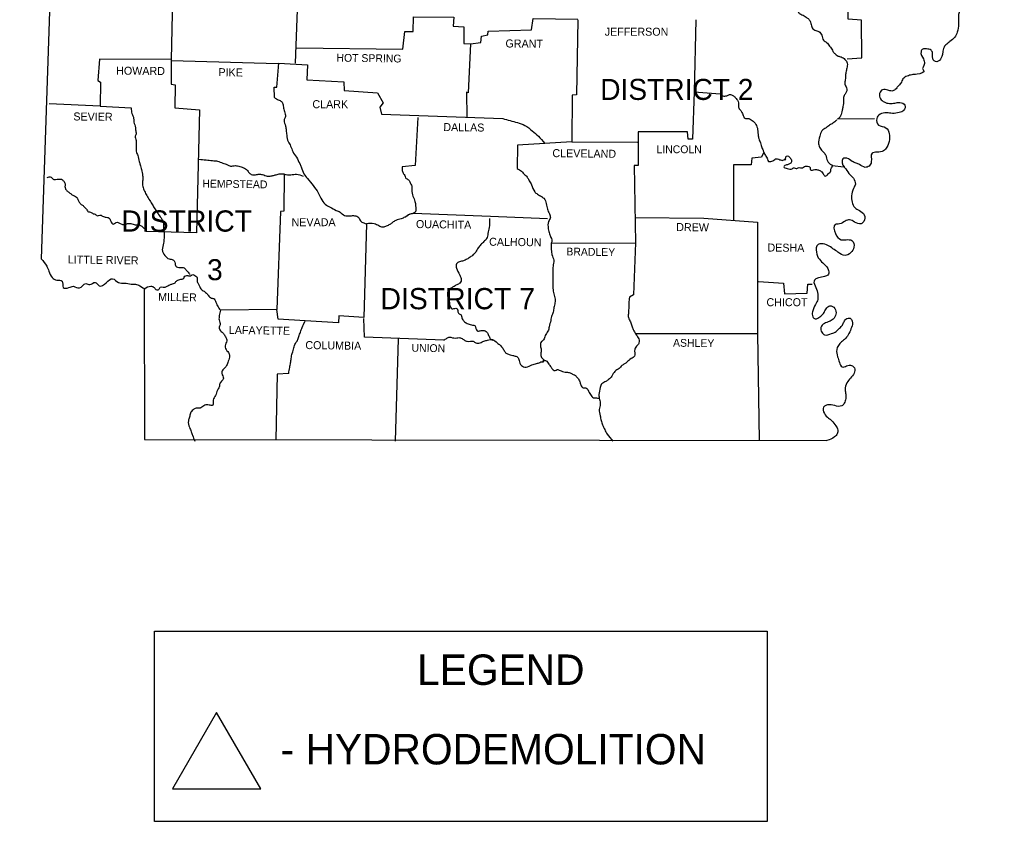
# Model space of a CAD drawing. Extents: x -17668 to 16999, y -17303 to 5867.
# Drawn here: x -17668 to -14783, y -11229 to -8859 of the extents above; entities that cross this region are included whole.
import ezdxf

# ---------------------------------------------------------------- set-up
doc = ezdxf.new("R2010")
doc.units = 0
for name, color, linetype in [('1', 7, 'Continuous'), ('2', 7, 'Continuous'), ('3', 7, 'Continuous'), ('48', 7, 'Continuous')]:
    doc.layers.add(name, color=color, linetype=linetype)

msp = doc.modelspace()

# ---------------------------------------------------------------- linework, layer by layer
at = {"layer": '1'}
msp.add_line((-15250.6, -9152.5), (-15140.6, -9150.8), dxfattribs=at)
for points in [[(-17667.8, -7158.5), (-17553.9, -8073.2), (-17603.4, -9566.3)], [(-15220.9, -8974.7), (-15178, -8972), (-15178.6, -8860.2), (-15218.7, -8857.5), (-15216.5, -8639), (-15251.2, -8634), (-15252.3, -8487.1), (-14782.8, -8483.8)], [(-16840.6, -8645.1), (-16853.3, -8987.9)], [(-17213.8, -8705.6), (-17219.8, -8976.4), (-17431.7, -8975.8), (-17436.7, -9038.6), (-17428.9, -9044.1), (-17429.5, -9114.5), (-17579.7, -9107.9)], [(-16849.4, -8942.2), (-16534.6, -8946.6), (-16528.6, -8894.4), (-16503.8, -8894.4), (-16503.3, -8850.3), (-16384.4, -8852), (-16385.5, -8878.4), (-16354.7, -8880.6), (-16354.7, -8929), (-16334.8, -8930.7)], [(-16334.8, -8930.7), (-16304, -8926.3), (-16301.8, -8907.6), (-16283.7, -8904.3), (-16282.6, -8893.3), (-16154.3, -8889.4), (-16149.4, -8855.8), (-16017.8, -8858)], [(-16017.8, -8859.1), (-16021.1, -9081.5), (-16033.8, -9082), (-16035.5, -9220.2)], [(-15668.9, -8859.7), (-15673.3, -9072.7), (-15596.8, -9078.7)], [(-16334.8, -8930.7), (-16341.4, -9074.9), (-16346.4, -9073.2), (-16345.9, -9148.1)], [(-17219.8, -8976.4), (-17219.8, -9049.6), (-17207.7, -9051.8), (-17208.8, -9120), (-17136.2, -9125.5), (-17145, -9489.3), (-17294.7, -9485.4)], [(-17218.7, -8980.2), (-16903.9, -8988.5)], [(-16914.4, -9089.2), (-16915.5, -9058.9), (-16906.7, -9058.4), (-16901.2, -8987.4), (-16816.4, -8992.9), (-16818.6, -9036.4), (-16709.1, -9042.4), (-16708.5, -9068.8), (-16609.5, -9074.9), (-16592.4, -9104.6), (-16602.9, -9117.8), (-16597.9, -9138.2), (-16239.1, -9151.4)], [(-15673.3, -9072.7), (-15678.3, -9212.5), (-15690.9, -9212.5), (-15693.1, -9191), (-15839.5, -9191), (-15839.5, -9221.8)], [(-17429.5, -9114.5), (-17338.1, -9120)], [(-16490, -9148.6), (-16498.3, -9290.1), (-16536.3, -9294.5)], [(-16114.7, -9225.1), (-16196.2, -9230.1), (-16196.7, -9298.9)], [(-16035.5, -9220.2), (-16115.8, -9225.1)], [(-16035.5, -9220.2), (-15840.6, -9221.3)], [(-15839.5, -9221.3), (-15839, -9290.1), (-15850.5, -9290.6), (-15847.2, -9519)], [(-15467.5, -9250.4), (-15474.1, -9265.3), (-15503.3, -9268.1), (-15504.9, -9287.9), (-15557.2, -9287.9), (-15557.7, -9452.4)], [(-15405.8, -9274.7), (-15404.2, -9273), (-15402.5, -9271.4), (-15402.5, -9271.4)], [(-16885.2, -9315.4), (-16886.3, -9424.9), (-16896.2, -9426), (-16907.2, -9716)], [(-16503.8, -9431.5), (-16276, -9439.8), (-16107, -9446.4)], [(-16642.5, -9462.3), (-16649.6, -9739.7), (-16723.9, -9734.8), (-16724.5, -9755.1), (-16823.6, -9749.1)], [(-15848.9, -9444.2), (-15644.7, -9445.8), (-15486.2, -9457.9)], [(-15486.2, -9457.9), (-15486.2, -9787), (-15481.8, -10103.5)], [(-16096, -9519.6), (-15847.2, -9519)], [(-15847.2, -9519), (-15852.7, -9672), (-15864.8, -9679.7)], [(-15483.4, -9633.5), (-15409.7, -9637.9), (-15406.4, -9669.8), (-15339.8, -9667.6), (-15337.1, -9640.6), (-15324.4, -9640.6)], [(-17299.1, -9655), (-17298, -10100.2), (-15280.9, -10103.5)], [(-16823.6, -9749.1), (-16903.4, -9744.7), (-16907.2, -9716), (-17074, -9717.7)], [(-16413.5, -9806.9), (-16648.5, -9798), (-16649.6, -9742.5)], [(-16548.4, -9803), (-16557.2, -10105.1)], [(-15843.9, -9786.5), (-15486.2, -9786.5)], [(-16872, -9904.8), (-16906.1, -9907), (-16910, -10100.7)]]:
    msp.add_lwpolyline(points, dxfattribs=at)
for points in [[(-14817.5, -8617), (-14830.2, -8632.9), (-14848.9, -8623), (-14848.9, -8609.8), (-14846.1, -8596.1), (-14852.7, -8587.3), (-14864.3, -8591.1), (-14864.3, -8608.2), (-14865.4, -8624.7), (-14868.7, -8648.4), (-14861, -8655.5), (-14843.4, -8657.7), (-14830.7, -8661), (-14823, -8673.7), (-14823.6, -8689.1), (-14829.6, -8703.9), (-14838.4, -8716), (-14852.2, -8720.5), (-14863.2, -8713.3), (-14867.6, -8699), (-14872.6, -8686.3), (-14881.9, -8677), (-14891.8, -8687.4), (-14894, -8706.7), (-14893.5, -8723.2), (-14893.5, -8745.8), (-14879.2, -8760.6), (-14870.4, -8777.7), (-14873.1, -8793.1), (-14883.6, -8811.3), (-14888, -8827.2), (-14892.4, -8848.7), (-14891.8, -8872.3), (-14895.7, -8895.5), (-14903.4, -8910.9), (-14917.7, -8923.5), (-14927, -8931.8), (-14934.7, -8940), (-14938.6, -8956.6), (-14941.3, -8968.1), (-14951.8, -8981.9), (-14960.1, -8983), (-14966.7, -8977.5), (-14968.9, -8968.1), (-14968.9, -8958.8), (-14973.3, -8949.4), (-14987, -8945.5), (-14998, -8946.1), (-15003, -8953.8), (-14995.8, -8975.3), (-14993.1, -8989), (-14996.9, -9007.7), (-14994.7, -9009.9), (-15014.5, -9020.4), (-15030.5, -9022), (-15043.7, -9025.9), (-15056.4, -9034.2), (-15062.4, -9046.3), (-15071.2, -9056.2), (-15078.9, -9065.5), (-15089.4, -9069.9), (-15101, -9067.7), (-15116.4, -9066.1), (-15125.2, -9077.1), (-15122.4, -9093), (-15112, -9102.4), (-15096.5, -9106.8), (-15080.6, -9105.7), (-15065.2, -9104), (-15050.9, -9111.8), (-15053.6, -9126.6), (-15067.4, -9133.8), (-15087.7, -9136), (-15104.3, -9134.3), (-15124.1, -9138.7), (-15134, -9151.4), (-15128.5, -9170.6), (-15107, -9178.3), (-15097.1, -9196.5), (-15096.5, -9213.6), (-15103.7, -9236.1), (-15113.6, -9246.6), (-15132.9, -9251), (-15147.7, -9253.7), (-15149.9, -9279.1), (-15156.5, -9291.7), (-15168.1, -9295.6), (-15184.6, -9287.3), (-15194.5, -9283.5), (-15206.6, -9278), (-15222, -9268.6), (-15233.6, -9270.3), (-15230.3, -9294.5), (-15229.2, -9295.6), (-15216, -9313.7), (-15202.8, -9328), (-15196.7, -9345.1)], [(-15387.7, -8794.2), (-15386, -8816.8), (-15372.8, -8820.1), (-15367.3, -8826.1), (-15364.6, -8838.8), (-15355.2, -8844.3), (-15342.6, -8852), (-15334.9, -8857.5), (-15329.3, -8866.3), (-15326, -8880.6), (-15317.2, -8890), (-15305.1, -8894.4), (-15296.3, -8904.8), (-15290.8, -8919.7), (-15282, -8926.3), (-15273.2, -8937.8), (-15268.8, -8942.8), (-15261.1, -8956), (-15253.4, -8962.6), (-15247.9, -8966.5), (-15239.1, -8969.2), (-15228.1, -8976.4), (-15220.9, -8987.4), (-15220.9, -8995.6), (-15223.7, -9008.3), (-15225.9, -9021.5), (-15227, -9036.4), (-15228.1, -9049.6), (-15223.1, -9060.6), (-15225.9, -9077.1), (-15231.4, -9085.9), (-15231.9, -9098), (-15233.6, -9116.2), (-15235.8, -9126.6), (-15240.7, -9143.7), (-15247.9, -9152.5)], [(-15596.8, -9078.7), (-15588.6, -9084.2), (-15577, -9083.7), (-15569.3, -9080.4), (-15563.2, -9080.9), (-15555, -9085.9), (-15549.5, -9092.5), (-15545.6, -9097.4), (-15542.9, -9105.1), (-15542.9, -9112.3), (-15540.1, -9122.2), (-15536.8, -9126.1), (-15532.4, -9133.2), (-15529.7, -9139.8), (-15528, -9144.2), (-15522, -9151.4), (-15516.5, -9150.8), (-15511.5, -9151.4), (-15504.9, -9155.2), (-15495, -9162.9), (-15493.4, -9165.1), (-15486.7, -9179.4), (-15485.6, -9188.3), (-15484.5, -9199.8), (-15482.3, -9210.8), (-15477.9, -9222.9), (-15475.7, -9231.2), (-15470.8, -9242.7), (-15467.5, -9250.4), (-15463.1, -9260.3), (-15456.5, -9271.4), (-15453.7, -9278), (-15444.4, -9277.4), (-15437.8, -9274.7), (-15432.8, -9270.3), (-15426.8, -9270.8), (-15420.2, -9273), (-15411.4, -9274.7), (-15405.8, -9271.4), (-15403.1, -9269.2), (-15402.5, -9264.2), (-15397.6, -9261.5), (-15392.1, -9265.3), (-15386, -9274.1), (-15386, -9279.6), (-15388.2, -9282.9), (-15395.4, -9287.3), (-15405.3, -9290.6), (-15408, -9294.5), (-15398.7, -9298.9), (-15383.8, -9300), (-15380, -9296.7), (-15370.1, -9299.4), (-15366.2, -9296.7), (-15353, -9297.2), (-15347, -9292.8), (-15334.9, -9293.4), (-15331, -9296.1), (-15331, -9301.1), (-15321.1, -9303.3), (-15313.9, -9301.6), (-15304.6, -9304.4), (-15296.3, -9308.8), (-15291.9, -9314.8), (-15286.4, -9321.4), (-15281.5, -9319.8), (-15277.6, -9314.8), (-15269.4, -9306), (-15269.4, -9300.5), (-15267.2, -9296.7), (-15264.4, -9291.2)], [(-16914.4, -9089.2), (-16905.6, -9094.7), (-16895.1, -9099.6), (-16889.6, -9107.9), (-16887.4, -9120.6), (-16883.5, -9134.3), (-16882.4, -9148.6), (-16885.7, -9156.3), (-16881.3, -9173.9), (-16879.7, -9186.1), (-16878, -9200.4), (-16873.6, -9219.6), (-16866.5, -9232.8), (-16859.9, -9248.8), (-16848.9, -9265.9), (-16839.5, -9284.6), (-16835.1, -9294.5), (-16826.9, -9314.8), (-16816.4, -9328.6), (-16799.9, -9349.5), (-16785, -9371), (-16776.8, -9386.9), (-16764.1, -9404.5), (-16749.8, -9413.3), (-16731.6, -9422.7), (-16720.1, -9428.2), (-16706.9, -9437.6), (-16689.8, -9438.7), (-16677.2, -9438.7), (-16665.6, -9443.6), (-16660.1, -9453.5), (-16650.2, -9460.1), (-16642.5, -9462.3)], [(-17338.1, -9120), (-17335.4, -9136.5), (-17330.4, -9150.8), (-17329.9, -9161.8), (-17324.9, -9178.3), (-17324.9, -9184.4), (-17323.3, -9196.5), (-17325.5, -9203.1), (-17322.7, -9216.3), (-17323.3, -9226.2), (-17323.3, -9234.5), (-17322.7, -9248.2), (-17318.3, -9260.3), (-17313.9, -9278.5), (-17311.2, -9287.9), (-17306.8, -9302.2), (-17304, -9319.8), (-17303.5, -9333), (-17304.6, -9345.1), (-17301.3, -9358.9), (-17295.2, -9372.6), (-17287.5, -9385.8), (-17278.2, -9400.7), (-17271.5, -9412.2), (-17263.3, -9424.9), (-17256.7, -9435.4), (-17246.8, -9448.6), (-17242.4, -9459.6), (-17242.4, -9475), (-17240.2, -9489.3), (-17240.7, -9505.3), (-17241.8, -9519.6), (-17245.7, -9539.4), (-17242.9, -9548.7), (-17232.5, -9562.5), (-17225.9, -9566.3), (-17214.3, -9568.5), (-17208.8, -9576.3), (-17205.5, -9587.8), (-17193.9, -9591.7), (-17181.3, -9592.8), (-17175.2, -9599.4), (-17167, -9608.2), (-17164.2, -9612.6)], [(-16239.1, -9151.4), (-16196.2, -9163.5), (-16174.1, -9171.7), (-16152.1, -9187.7), (-16134, -9203.7), (-16115.8, -9224)], [(-15251.7, -9155.8), (-15263.3, -9165.1), (-15273.2, -9170.6), (-15283.7, -9178.3), (-15296.3, -9187.7), (-15302.4, -9203.7), (-15305.7, -9225.7), (-15301.3, -9238.9), (-15291.4, -9250.4), (-15284.8, -9259.8), (-15279.8, -9276.3), (-15267.7, -9287.9), (-15263.9, -9289.5)], [(-17137.3, -9271.9), (-17116.3, -9273.6), (-17097.1, -9275.8), (-17082.2, -9277.4), (-17066.8, -9282.9), (-17053.1, -9287.9), (-17044.3, -9291.7), (-17029.4, -9290.6), (-17016.7, -9293.4), (-17002.4, -9298.3), (-16992, -9307.7), (-16985.4, -9314.8), (-16972.7, -9317.6), (-16962.2, -9315.9), (-16949.6, -9317), (-16935.3, -9321.4), (-16923.7, -9320.9), (-16914.4, -9318.7), (-16903.4, -9315.9), (-16889.6, -9314.8), (-16879.1, -9317), (-16865.4, -9317.6), (-16849.4, -9315.9), (-16829.6, -9321.4)], [(-16536.3, -9294.5), (-16536.3, -9304.9), (-16532.4, -9314.8), (-16528.6, -9319.2), (-16526.9, -9326.4), (-16522, -9329.7), (-16514.8, -9336.3), (-16511, -9345.7), (-16508.2, -9351.7), (-16508.2, -9359.4), (-16507.7, -9367.1), (-16506.6, -9376.5), (-16500, -9393), (-16498.3, -9399.6), (-16497.2, -9405.1), (-16496.6, -9414.4), (-16496.6, -9425.5), (-16503.8, -9431.5)], [(-16196.7, -9298.9), (-16184, -9307.1), (-16173.6, -9318.1), (-16165.9, -9326.4), (-16160.9, -9335.7), (-16154.3, -9346.8), (-16145, -9367.7), (-16136.7, -9374.8), (-16125.2, -9382), (-16118, -9386.9), (-16110.9, -9402.9), (-16107.5, -9418.9), (-16101.5, -9433.2), (-16098.7, -9444.2), (-16103.7, -9455.2), (-16104.8, -9477.2), (-16101.5, -9492), (-16097.1, -9503.1), (-16094.3, -9515.7), (-16096, -9519.6)], [(-17586.3, -9325.3), (-17574.2, -9324.7), (-17566, -9331.9), (-17561, -9331.3), (-17552.2, -9330.2), (-17544, -9330.8), (-17537.9, -9335.7), (-17533, -9344.6), (-17533.5, -9352.8), (-17533, -9356.1), (-17529.1, -9363.3), (-17522.5, -9368.8), (-17515.4, -9374.3), (-17508.7, -9378.7), (-17497.7, -9385.8), (-17496.6, -9388), (-17492.2, -9396.8), (-17486.7, -9404), (-17480.1, -9408.4), (-17473, -9416.1), (-17469.7, -9419.4), (-17464.2, -9427.1), (-17458.1, -9427.7), (-17449.9, -9432.6), (-17443.8, -9434.3), (-17437.2, -9438.7), (-17430.6, -9436.5), (-17422.3, -9439.8), (-17411.3, -9443.1), (-17405.3, -9444.2), (-17398.1, -9454.6), (-17391, -9463.4), (-17382.2, -9458.5), (-17365.7, -9463.4), (-17355.2, -9464), (-17345.8, -9461.2), (-17338.7, -9461.8), (-17325.5, -9465.1), (-17317.2, -9465.1), (-17308.4, -9468.4), (-17300.2, -9475), (-17294.7, -9482.1), (-17294.7, -9485.4)], [(-15196.7, -9345.1), (-15202.2, -9357.8), (-15208.3, -9379.8), (-15206.6, -9398.5), (-15198.4, -9414.4), (-15185.2, -9423.3), (-15170.8, -9435.9), (-15171.9, -9455.2), (-15180.2, -9462.3), (-15199.5, -9457.4), (-15214.3, -9450.8), (-15227, -9454.6), (-15244, -9462.9), (-15256.7, -9464.5), (-15256.2, -9490.9), (-15239.1, -9509.7), (-15224.2, -9509.7), (-15207.2, -9511.9), (-15201.1, -9531.7), (-15211, -9548.2), (-15227.5, -9556.4), (-15248.4, -9546.5), (-15263.3, -9536.1), (-15278.2, -9526.2), (-15296.9, -9521.2), (-15307.3, -9523.4), (-15312.3, -9546.5), (-15303.5, -9567.4), (-15289.2, -9581.8), (-15276, -9600.5), (-15278.2, -9614.2), (-15288.1, -9618.1), (-15305.7, -9621.9), (-15316.1, -9627.4), (-15318.9, -9631.8), (-15313.4, -9650.6), (-15308.4, -9670.9), (-15308.4, -9686.3), (-15314.5, -9700.6), (-15323.8, -9722.6), (-15322.7, -9737), (-15316.1, -9743.6), (-15307.9, -9741.4), (-15296.9, -9733.7), (-15289.7, -9724.8), (-15283.7, -9713.8), (-15272.1, -9704.5), (-15257.8, -9712.7), (-15254.5, -9729.8), (-15262.8, -9744.7), (-15274.3, -9751.3), (-15288.6, -9756.8), (-15299.1, -9768.9), (-15296.3, -9783.2), (-15288.1, -9790.9), (-15267.7, -9787), (-15253.9, -9781), (-15246.2, -9773.3), (-15236.9, -9763.9), (-15231.9, -9754.6), (-15224.8, -9744.7), (-15212.1, -9741.9), (-15206.1, -9750.2), (-15208.3, -9768.9), (-15216, -9786.5), (-15226.4, -9801.3), (-15238, -9811.8), (-15252.3, -9834.4), (-15249.5, -9855.3), (-15244, -9872.3), (-15236.3, -9885.6), (-15223.1, -9882.8), (-15208.3, -9881.1), (-15199.5, -9888.3), (-15200.6, -9903.7), (-15211.6, -9918.6), (-15222, -9932.9), (-15227.5, -9952.7), (-15225.3, -9966.5), (-15225.3, -9979.1), (-15229.7, -9992.9), (-15237.4, -10000.6), (-15257.8, -10000), (-15279.3, -9997.8), (-15290.8, -10004.4), (-15288.6, -10023.1), (-15276, -10036.9), (-15267.2, -10044.1), (-15254.5, -10059.5), (-15249, -10072.1), (-15250.6, -10083.1), (-15258.4, -10092.5), (-15280.9, -10103.5)], [(-16514.3, -9433.7), (-16528.6, -9443.1), (-16539.6, -9447.5), (-16547.8, -9450.2), (-16555.5, -9452.4), (-16565.4, -9459), (-16573.1, -9464.5), (-16583.6, -9469.5), (-16593.5, -9472.8), (-16605.6, -9468.9), (-16612.2, -9465.1), (-16619.4, -9462.3), (-16642.5, -9462.3)], [(-16528.6, -9443.1), (-16514.3, -9433.7), (-16503.8, -9431.5)], [(-16278.2, -9446.4), (-16279.3, -9473.9), (-16283.1, -9490.9), (-16287, -9506.4), (-16295.2, -9515.2), (-16304, -9524), (-16312.3, -9533.9), (-16319.4, -9546), (-16326.6, -9553.7), (-16335.9, -9561.4), (-16345.3, -9566.9), (-16355.8, -9571.8), (-16367.3, -9574.6), (-16375.6, -9580.7), (-16376.1, -9593.9), (-16366.8, -9612.6), (-16363.5, -9621.4), (-16362.4, -9631.8), (-16366.2, -9637.9), (-16375, -9642.8), (-16385.5, -9648.9), (-16394.8, -9654.4), (-16401.4, -9663.8), (-16402.5, -9676.4), (-16398.1, -9691.3), (-16396.5, -9700.1), (-16389.3, -9713.8), (-16383.8, -9713.3), (-16373.9, -9713.8), (-16372.8, -9716.6), (-16372.3, -9719.3), (-16370.1, -9726.5), (-16361.8, -9732.6), (-16360.7, -9738.1), (-16355.8, -9748.5), (-16347.5, -9755.7), (-16341.4, -9757.9), (-16328.8, -9761.7), (-16322.2, -9763.4), (-16315, -9779.3), (-16306.2, -9778.8), (-16299.6, -9777.7), (-16288.6, -9780.4), (-16283.7, -9787), (-16278.7, -9798), (-16272.1, -9805.8), (-16267.7, -9805.8)], [(-16096, -9519.6), (-16093.8, -9553.7), (-16088.8, -9570.2), (-16090.5, -9587.8), (-16091, -9604.9), (-16091, -9620.3), (-16091, -9635.1), (-16091, -9650.6), (-16089.9, -9661.6), (-16086.1, -9677.5), (-16084.4, -9692.4), (-16087.7, -9706.7), (-16089.4, -9719.9), (-16093.8, -9733.1), (-16097.6, -9748), (-16102, -9767.2), (-16105.9, -9779.9), (-16113.6, -9793.1), (-16118.6, -9805.2), (-16126.3, -9812.9), (-16127.4, -9826.1), (-16125.7, -9838.2), (-16126.8, -9849.2), (-16123, -9859.7), (-16113.1, -9866.8)], [(-17603.4, -9566.3), (-17587.5, -9587.3), (-17580.8, -9602.1), (-17571.5, -9621.4), (-17557.7, -9629.1), (-17541.8, -9631.8), (-17538.5, -9650.6), (-17522, -9651.1), (-17508.7, -9647.2), (-17490.6, -9652.2), (-17471.3, -9639), (-17460.3, -9642.3), (-17444.4, -9635.7), (-17432.3, -9645.6), (-17411.3, -9636.8), (-17392.6, -9624.7), (-17375, -9636.2), (-17358, -9637.9), (-17337.6, -9640.6), (-17321.6, -9641.7), (-17307.3, -9648.9), (-17296.9, -9656.1), (-17299.1, -9655)], [(-17299.1, -9655), (-17279.8, -9646.7), (-17271.5, -9649.4), (-17264.4, -9656.6), (-17256.1, -9656.6), (-17251.7, -9650), (-17243.5, -9649.4), (-17236.9, -9650), (-17229.7, -9645.6), (-17223.7, -9642.8), (-17215.4, -9640.1), (-17209.4, -9637.9), (-17203.9, -9631.8), (-17193.9, -9626.9), (-17182.4, -9623), (-17179.1, -9617.5), (-17173.6, -9615.3), (-17162.6, -9615.9), (-17155.4, -9612.6), (-17149.4, -9615.3), (-17143.9, -9619.2), (-17142.8, -9633.5), (-17138.4, -9641.2), (-17131.8, -9655), (-17122.4, -9662.1), (-17113.6, -9669.3), (-17110.3, -9673.7), (-17100.9, -9681.9), (-17092.7, -9684.7), (-17088.8, -9690.7), (-17082.8, -9705), (-17074, -9717.7)], [(-15864.8, -9679.7), (-15866.5, -9696.8), (-15867, -9712.7), (-15868.1, -9728.2), (-15868.1, -9739.7), (-15861.5, -9752.4), (-15857.7, -9764.5), (-15853.8, -9774.9), (-15846.1, -9788.7), (-15839, -9799.1), (-15836.8, -9814), (-15841.2, -9821.7), (-15849.4, -9833.3), (-15850, -9854.2), (-15859.9, -9860.8), (-15872.5, -9871.8), (-15879.7, -9876.7), (-15887.4, -9881.7), (-15895.7, -9890.5), (-15907.8, -9898.8), (-15916.6, -9912.5), (-15926.5, -9923), (-15934.7, -9928.5), (-15946.3, -9935.6), (-15951.2, -9946.6), (-15955.1, -9967), (-15953.4, -9981.9), (-15951.2, -9995.1), (-15954, -10011.6), (-15951.2, -10029.7), (-15948.5, -10044.1), (-15944.1, -10056.7), (-15938, -10071), (-15930.3, -10084.2), (-15913.8, -10104.6)], [(-17074, -9717.7), (-17077.3, -9733.7), (-17077.8, -9746.3), (-17075.1, -9761.2), (-17077.8, -9768.3), (-17073.4, -9778.8), (-17065.2, -9787), (-17059.1, -9795.8), (-17055.3, -9808.5), (-17060.2, -9822.8), (-17054.7, -9837.7), (-17049.8, -9843.2), (-17047, -9852), (-17050.9, -9869), (-17055.8, -9881.7), (-17066.8, -9894.4), (-17070.1, -9900.4), (-17068.5, -9908.7), (-17065.7, -9921.9), (-17068.5, -9925.7), (-17075.6, -9935.1), (-17077.8, -9945.5), (-17082.8, -9954.3), (-17088.3, -9970.3), (-17095.4, -9983.5), (-17096.5, -9998.4), (-17107.5, -9998.4), (-17120.2, -9998.4), (-17131.8, -10006.6), (-17142.2, -10007.2), (-17154.9, -10012.1), (-17162.6, -10022.6), (-17165.3, -10034.1), (-17168.6, -10045.2), (-17165.3, -10063.9), (-17160.4, -10077.1), (-17156.5, -10087.5), (-17149.9, -10104.6)], [(-16872, -9904.8), (-16869.2, -9887.2), (-16866.5, -9873.4), (-16864.8, -9860.2), (-16861.5, -9845.4), (-16856.6, -9829.4), (-16852.2, -9816.2), (-16846.1, -9806.9), (-16842.3, -9795.8), (-16837.3, -9782.6), (-16832.4, -9768.9), (-16823.6, -9751.3)], [(-16413.5, -9806.9), (-16404.7, -9800.8), (-16396.5, -9797.5), (-16388.2, -9799.1), (-16379.4, -9800.2), (-16371.7, -9799.1), (-16361.8, -9800.8), (-16353.6, -9805.8), (-16344.2, -9809.6), (-16334.8, -9809.6), (-16326.6, -9809.6), (-16319.4, -9814.6), (-16306.2, -9814), (-16295.2, -9809.6), (-16284.2, -9806.3), (-16269.4, -9804.6), (-16256.1, -9814), (-16246.8, -9821.7), (-16239.1, -9830.5), (-16233.6, -9840.4), (-16227.5, -9845.9), (-16217.6, -9849.8), (-16209.9, -9851.4), (-16200.6, -9854.2), (-16195.6, -9856.4), (-16191.2, -9866.8), (-16184, -9881.1), (-16170.3, -9886.1), (-16153.2, -9879.5), (-16139.5, -9875.6), (-16129.6, -9872.3), (-16123.5, -9870.1), (-16118, -9869.6), (-16119.7, -9868.5), (-16113.1, -9866.8), (-16107, -9871.2), (-16103.1, -9877.3), (-16096.5, -9886.1), (-16090.5, -9893.8), (-16084.4, -9896.6), (-16078.4, -9893.3), (-16070.1, -9896), (-16063, -9898.8), (-16054.7, -9901), (-16047.6, -9901.5), (-16038.2, -9903.7), (-16031, -9907.6), (-16024.4, -9911.4), (-16017.8, -9918.6), (-16011.2, -9929.6), (-16009, -9938.4), (-16001.3, -9947.2), (-15994.2, -9947.2), (-15983.7, -9961.5), (-15979.9, -9967), (-15971.6, -9976.9), (-15965.6, -9976.9), (-15954, -9979.1)]]:
    msp.add_spline(points, degree=3, dxfattribs=at)
at = {"layer": '3'}
msp.add_line((-15265.5, -9290.1), (-15230.8, -9294.5), dxfattribs=at)
at = {"layer": '48'}
for p, q in [((-17085.4, -10906.8), (-17216, -11133)), ((-16954.8, -11133), (-17085.4, -10906.8)), ((-17216, -11133), (-16954.8, -11133))]:
    msp.add_line(p, q, dxfattribs=at)
msp.add_lwpolyline([(-17268.7, -10666.7), (-15458, -10666.7), (-15458, -11229.3), (-17268.7, -11229.3)], close=True, dxfattribs=at)

# ---------------------------------------------------------------- texts
at = {"layer": '2'}
for s, height, p in [('JEFFERSON', 23.67, (-15938, -8906.5)), ('CLARK', 23.67, (-16802, -9120.7)), ('LINCOLN', 23.11, (-15785, -9253.7)), ('NEVADA', 23.67, (-16863.7, -9469.5)), ('CHICOT', 23.67, (-15459.8, -9706.1))]:
    msp.add_text(s, height=height, dxfattribs=at).set_placement(p)
for s, height, rotation, p in [('GRANT', 23.67, 359.4032, (-16231.4, -8941.1)), ('HOT SPRING', 23.11, 359.2216, (-16731.1, -8983)), ('HOWARD', 23.67, 359.5145, (-17382.2, -9021.5)), ('PIKE', 23.66, 359.0452, (-17080, -9025.9)), ('SEVIER', 23.67, 359.4271, (-17508.7, -9156.9)), ('DALLAS', 23.66, 359.2462, (-16415.2, -9188.3)), ('CLEVELAND', 23.67, 359.3377, (-16092.7, -9265.3)), ('HEMPSTEAD', 23.11, 359.1885, (-17127.4, -9355)), ('OUACHITA', 23.67, 359.2043, (-16496.1, -9475)), ('DREW', 23.66, 359.2258, (-15726.7, -9483.8)), ('CALHOUN', 23.67, 359.3634, (-16279.8, -9527.3)), ('BRADLEY', 23.11, 359.1449, (-16051.4, -9555.9)), ('DESHA', 23.66, 359.3704, (-15457, -9544.3)), ('LITTLE RIVER', 23.666, 359.1697, (-17525.3, -9579.6)), ('MILLER', 23.66, 359.1319, (-17258.3, -9690.2)), ('LAFAYETTE', 23.66, 359.1839, (-17049.2, -9788.1)), ('COLUMBIA', 23.66, 359.2125, (-16823, -9832.7)), ('ASHLEY', 23.11, 359.2361, (-15736.1, -9825.6)), ('UNION', 23.11, 358.9584, (-16509.3, -9840.4))]:
    msp.add_text(s, height=height, rotation=rotation, dxfattribs=at).set_placement(p)
at = {"layer": '3'}
for s, height, p in [('DISTRICT 2', 62.19, (-15951.2, -9096.3)), ('DISTRICT', 62.74, (-17367.1, -9485.6)), ('3', 62.2, (-17113.4, -9629.2)), ('DISTRICT 7', 62.74, (-16600.8, -9715.1))]:
    msp.add_text(s, height=height, dxfattribs=at).set_placement(p)
at = {"layer": '48'}
for s, p in [('LEGEND', (-16492.5, -10825.6)), ('- HYDRODEMOLITION', (-16895.8, -11060.6))]:
    msp.add_text(s, height=90, dxfattribs=at).set_placement(p)

doc.saveas('drawing.dxf')
